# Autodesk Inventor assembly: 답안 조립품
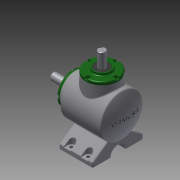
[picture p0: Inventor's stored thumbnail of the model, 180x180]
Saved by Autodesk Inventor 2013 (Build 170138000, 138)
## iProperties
Created: 2017-04
Part Number: 답안 조립품
Document SubType Name: Assembly
Designer: Administrator
Author: Administrator
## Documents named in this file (14)
- C:\Users\Administrator\Desktop\470408V1005\답안 조립품.iam
- C:\Users\Administrator\Desktop\470408V1005\1.본체.ipt
- C:\Users\Administrator\Desktop\470408V1005\메인 베벨기어.ipt
- C:\Users\Administrator\Desktop\470408V1005\메인 축.ipt
- 메인 축.ipt
- C:\Users\Administrator\Desktop\470408V1005\베어링 6203.ipt
- C:\Users\Administrator\Desktop\470408V1005\볼트 M4.ipt
- C:\Users\Administrator\Desktop\470408V1005\서브 베벨기어.ipt
- C:\Users\Administrator\Desktop\470408V1005\서브 축.ipt
- 서브 축.ipt
- C:\Users\Administrator\Desktop\470408V1005\오일실 17 32 8.ipt
- C:\Users\Administrator\Desktop\470408V1005\커버.ipt
- C:\Users\Administrator\Desktop\470408V1005\키 4x4.ipt
- C:\Users\Administrator\Desktop\470408V1005\키 5x5.ipt
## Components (1 placed, 1 different names)
1. 1.본체:1
